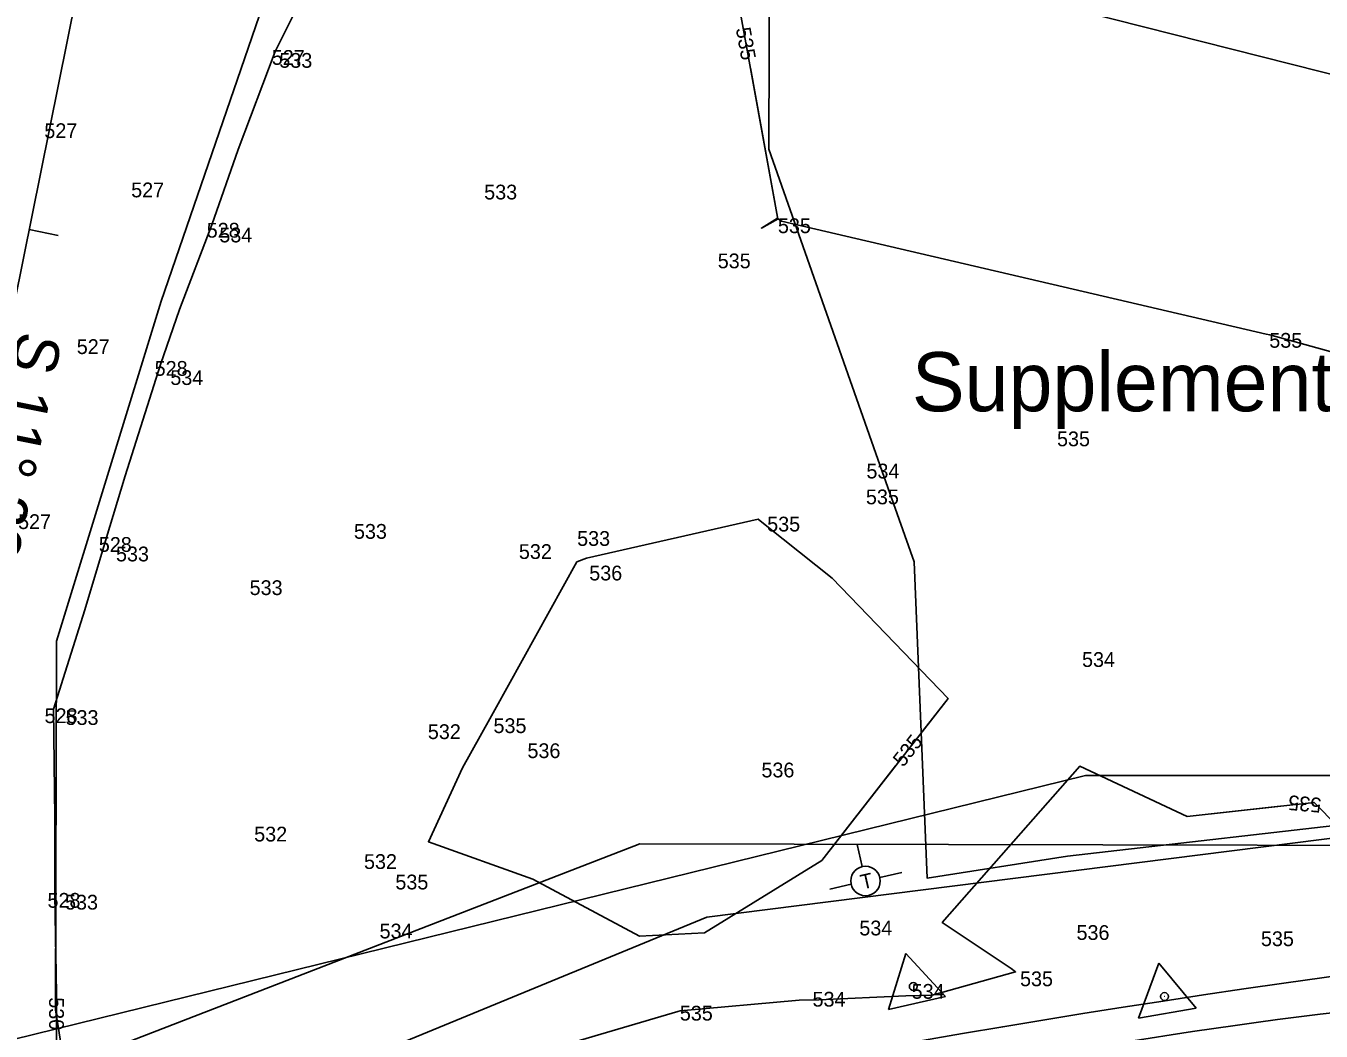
# Model space of a CAD drawing. Extents: x 1787461 to 1970323, y 938412 to 1118748.
# Drawn here: x 1967824.4 to 1967999.8, y 1117941.2 to 1118077.3 of the extents above; entities that cross this region are included whole.
import ezdxf

# ---------------------------------------------------------------- set-up
doc = ezdxf.new("R2010")
doc.units = 0
for name, color, linetype in [('Default', 7, 'Continuous'), ('HHA ADDITIONAL XSs', 7, 'Continuous'), ('Level 1', 7, 'Continuous'), ('RD_EX_DV_Prop', 7, 'Continuous'), ('RD_EX_Fence_Other', 7, 'Continuous'), ('RD_EX_H2O', 7, 'Continuous'), ('RD_EX_Road', 7, 'Continuous'), ('RD_EX_UT', 7, 'Continuous'), ('RD_EX_VEG', 7, 'Continuous'), ('RD_HC_CL', 7, 'Continuous'), ('RD_HC_Data', 7, 'Continuous'), ('RD_HC_Data_Rel', 7, 'Continuous'), ('RD_HC_Data_Tic', 7, 'Continuous'), ('RD_PD_Final_TrvlWay', 7, 'Continuous'), ('RD_SMD_Locator', 7, 'Continuous')]:
    doc.layers.add(name, color=color, linetype=linetype)

msp = doc.modelspace()

# ---------------------------------------------------------------- linework, layer by layer
at = {"layer": 'Default'}
for points in [[(1967828.54, 1117946.2), (1967828.33, 1117959.79), (1967828.34, 1117970.11), (1967828.12, 1117984.79), (1967832.39, 1117998.26), (1967835.19, 1118007.59), (1967837.84, 1118016.4), (1967842.61, 1118031.47), (1967845.22, 1118038.9), (1967849.58, 1118050.38), (1967853.13, 1118060.57), (1967858.16, 1118073.86), (1967863.11, 1118083.83), (1967868.71, 1118095.35), (1967874.84, 1118107.68), (1967879.73, 1118117.72), (1967880.44, 1118118.26), (1967881.88, 1118119.35), (1967891.88, 1118127.03), (1967894.42, 1118128.95)], [(1967828.54, 1117946.2), (1967828.33, 1117959.79), (1967828.34, 1117970.11), (1967828.12, 1117984.79), (1967832.39, 1117998.26), (1967835.19, 1118007.59), (1967837.84, 1118016.4), (1967842.61, 1118031.47), (1967845.22, 1118038.9), (1967849.58, 1118050.38), (1967853.13, 1118060.57), (1967858.16, 1118073.86), (1967863.11, 1118083.83), (1967868.71, 1118095.35), (1967874.84, 1118107.68), (1967879.73, 1118117.72), (1967880.44, 1118118.26), (1967881.88, 1118119.35), (1967891.88, 1118127.03), (1967894.42, 1118128.95)], [(1967828.54, 1117946.2), (1967828.33, 1117959.79), (1967828.34, 1117970.11), (1967828.12, 1117984.79), (1967832.39, 1117998.26), (1967835.19, 1118007.59), (1967837.84, 1118016.4), (1967842.61, 1118031.47), (1967845.22, 1118038.9), (1967849.58, 1118050.38), (1967853.13, 1118060.57), (1967858.16, 1118073.86), (1967863.11, 1118083.83), (1967868.71, 1118095.35), (1967874.84, 1118107.68), (1967879.73, 1118117.72), (1967880.44, 1118118.26), (1967881.88, 1118119.35), (1967891.88, 1118127.03), (1967894.42, 1118128.95)], [(1967828.54, 1117946.2), (1967828.33, 1117959.79), (1967828.34, 1117970.11), (1967828.12, 1117984.79), (1967832.39, 1117998.26), (1967835.19, 1118007.59), (1967837.84, 1118016.4), (1967842.61, 1118031.47), (1967845.22, 1118038.9), (1967849.58, 1118050.38), (1967853.13, 1118060.57), (1967858.16, 1118073.86), (1967863.11, 1118083.83), (1967868.71, 1118095.35), (1967874.84, 1118107.68), (1967879.73, 1118117.72), (1967880.44, 1118118.26), (1967881.88, 1118119.35), (1967891.88, 1118127.03), (1967894.42, 1118128.95)], [(1967828.54, 1117946.2), (1967828.33, 1117959.79), (1967828.34, 1117970.11), (1967828.12, 1117984.79), (1967832.39, 1117998.26), (1967835.19, 1118007.59), (1967837.84, 1118016.4), (1967842.61, 1118031.47), (1967845.22, 1118038.9), (1967849.58, 1118050.38), (1967853.13, 1118060.57), (1967858.16, 1118073.86), (1967863.11, 1118083.83), (1967868.71, 1118095.35), (1967874.84, 1118107.68), (1967879.73, 1118117.72), (1967880.44, 1118118.26), (1967881.88, 1118119.35), (1967891.88, 1118127.03), (1967894.42, 1118128.95)], [(1967828.54, 1117946.2), (1967828.33, 1117959.79), (1967828.34, 1117970.11), (1967828.12, 1117984.79), (1967832.39, 1117998.26), (1967835.19, 1118007.59), (1967837.84, 1118016.4), (1967842.61, 1118031.47), (1967845.22, 1118038.9), (1967849.58, 1118050.38), (1967853.13, 1118060.57), (1967858.16, 1118073.86), (1967863.11, 1118083.83), (1967868.71, 1118095.35), (1967874.84, 1118107.68), (1967879.73, 1118117.72), (1967880.44, 1118118.26), (1967881.88, 1118119.35), (1967891.88, 1118127.03), (1967894.42, 1118128.95)], [(1967915.91, 1118108.1), (1967926.19, 1118051.4), (1967926.18, 1118051.26), (1967924.01, 1118049.94), (1967926.27, 1118051.18), (1967926.72, 1118050.88), (1967992.39, 1118035.55), (1967992.88, 1118035.49), (1968026.69, 1118026.12), (1968042.97, 1118005.82), (1968041.62, 1117976.71), (1968051.06, 1117991.91), (1968062.41, 1117984.73), (1968055.12, 1118002.49), (1968107.9, 1117976.3), (1968127.27, 1117968.76), (1968135.27, 1117966.88), (1968158.58, 1117958.62), (1968183.42, 1117953.49), (1968183.93, 1117953.55), (1968186.05, 1117953.11), (1968208.47, 1117951.67)], [(1967828.54, 1117935.04), (1967828.55, 1117945.4), (1967828.33, 1117959.79), (1967828.34, 1117970.11), (1967828.12, 1117984.79), (1967832.39, 1117998.26), (1967835.19, 1118007.59), (1967837.84, 1118016.4), (1967842.61, 1118031.47), (1967845.22, 1118038.9), (1967849.58, 1118050.38), (1967853.13, 1118060.57), (1967858.16, 1118073.86), (1967863.11, 1118083.83)], [(1967922.52, 1118071.64), (1967926.19, 1118051.4), (1967926.18, 1118051.26), (1967924.01, 1118049.94), (1967926.27, 1118051.18), (1967926.72, 1118050.88), (1967992.39, 1118035.55), (1967992.88, 1118035.49), (1968026.69, 1118026.12), (1968042.97, 1118005.82), (1968041.62, 1117976.71), (1968049.78, 1117989.85)], [(1967922.52, 1118071.64), (1967926.19, 1118051.4), (1967926.18, 1118051.26), (1967924.01, 1118049.94), (1967926.27, 1118051.18), (1967926.72, 1118050.88), (1967992.39, 1118035.55), (1967992.88, 1118035.49), (1968026.69, 1118026.12), (1968042.97, 1118005.82), (1968041.62, 1117976.71), (1968049.78, 1117989.85)], [(1967922.52, 1118071.64), (1967926.19, 1118051.4), (1967926.18, 1118051.26), (1967924.01, 1118049.94), (1967926.27, 1118051.18), (1967926.72, 1118050.88), (1967992.39, 1118035.55), (1967992.88, 1118035.49), (1968026.69, 1118026.12), (1968042.97, 1118005.82), (1968041.62, 1117976.71), (1968049.78, 1117989.85)], [(1967922.52, 1118071.64), (1967926.19, 1118051.4), (1967926.18, 1118051.26), (1967924.01, 1118049.94), (1967926.27, 1118051.18), (1967926.72, 1118050.88), (1967992.39, 1118035.55), (1967992.88, 1118035.49), (1968026.69, 1118026.12), (1968042.97, 1118005.82), (1968041.62, 1117976.71), (1968049.78, 1117989.85)], [(1967922.52, 1118071.64), (1967926.19, 1118051.4), (1967926.18, 1118051.26), (1967924.01, 1118049.94), (1967926.27, 1118051.18), (1967926.72, 1118050.88), (1967992.39, 1118035.55), (1967992.88, 1118035.49), (1968026.69, 1118026.12), (1968042.97, 1118005.82), (1968041.62, 1117976.71), (1968049.78, 1117989.85)], [(1967922.52, 1118071.64), (1967926.19, 1118051.4), (1967926.18, 1118051.26), (1967924.01, 1118049.94), (1967926.27, 1118051.18), (1967926.72, 1118050.88), (1967992.39, 1118035.55), (1967992.88, 1118035.49), (1968026.69, 1118026.12), (1968042.97, 1118005.82), (1968041.62, 1117976.71), (1968049.78, 1117989.85)], [(1967887.9, 1117984.71), (1967887.24, 1117983.5), (1967883.53, 1117976.86), (1967878.92, 1117966.83), (1967893.06, 1117961.78), (1967907.49, 1117954.05), (1967916.29, 1117954.52), (1967932.22, 1117964.31), (1967949.29, 1117986.25), (1967933.58, 1118002.54), (1967924.77, 1118009.55), (1967923.57, 1118010.51), (1967900.34, 1118005.25), (1967899.03, 1118004.73), (1967887.9, 1117984.71)], [(1967945.86, 1117981.85), (1967949.29, 1117986.25), (1967933.58, 1118002.54), (1967924.77, 1118009.55), (1967923.57, 1118010.51), (1967900.34, 1118005.25), (1967899.03, 1118004.73), (1967887.9, 1117984.71)], [(1967945.86, 1117981.85), (1967949.29, 1117986.25), (1967933.58, 1118002.54), (1967924.77, 1118009.55), (1967923.57, 1118010.51), (1967900.34, 1118005.25), (1967899.03, 1118004.73), (1967887.9, 1117984.71)], [(1967945.86, 1117981.85), (1967949.29, 1117986.25), (1967933.58, 1118002.54), (1967924.77, 1118009.55), (1967923.57, 1118010.51), (1967900.34, 1118005.25), (1967899.03, 1118004.73), (1967887.9, 1117984.71)], [(1967945.86, 1117981.85), (1967949.29, 1117986.25), (1967933.58, 1118002.54), (1967924.77, 1118009.55), (1967923.57, 1118010.51), (1967900.34, 1118005.25), (1967899.03, 1118004.73), (1967887.9, 1117984.71)], [(1967945.86, 1117981.85), (1967949.29, 1117986.25), (1967933.58, 1118002.54), (1967924.77, 1118009.55), (1967923.57, 1118010.51), (1967900.34, 1118005.25), (1967899.03, 1118004.73), (1967887.9, 1117984.71)], [(1967945.86, 1117981.85), (1967949.29, 1117986.25), (1967933.58, 1118002.54), (1967924.77, 1118009.55), (1967923.57, 1118010.51), (1967900.34, 1118005.25), (1967899.03, 1118004.73), (1967887.9, 1117984.71)], [(1967887.9, 1117984.71), (1967887.24, 1117983.5), (1967883.53, 1117976.86), (1967878.92, 1117966.83), (1967893.06, 1117961.78), (1967907.49, 1117954.05), (1967916.29, 1117954.52), (1967932.22, 1117964.31), (1967942.17, 1117977.11)], [(1967887.9, 1117984.71), (1967887.24, 1117983.5), (1967883.53, 1117976.86), (1967878.92, 1117966.83), (1967893.06, 1117961.78), (1967907.49, 1117954.05), (1967916.29, 1117954.52), (1967932.22, 1117964.31), (1967942.17, 1117977.11)], [(1967887.9, 1117984.71), (1967887.24, 1117983.5), (1967883.53, 1117976.86), (1967878.92, 1117966.83), (1967893.06, 1117961.78), (1967907.49, 1117954.05), (1967916.29, 1117954.52), (1967932.22, 1117964.31), (1967942.17, 1117977.11)], [(1967887.9, 1117984.71), (1967887.24, 1117983.5), (1967883.53, 1117976.86), (1967878.92, 1117966.83), (1967893.06, 1117961.78), (1967907.49, 1117954.05), (1967916.29, 1117954.52), (1967932.22, 1117964.31), (1967942.17, 1117977.11)], [(1967887.9, 1117984.71), (1967887.24, 1117983.5), (1967883.53, 1117976.86), (1967878.92, 1117966.83), (1967893.06, 1117961.78), (1967907.49, 1117954.05), (1967916.29, 1117954.52), (1967932.22, 1117964.31), (1967942.17, 1117977.11)], [(1967887.9, 1117984.71), (1967887.24, 1117983.5), (1967883.53, 1117976.86), (1967878.92, 1117966.83), (1967893.06, 1117961.78), (1967907.49, 1117954.05), (1967916.29, 1117954.52), (1967932.22, 1117964.31), (1967942.17, 1117977.11)], [(1967994.28, 1117971.65), (1967981.7, 1117970.25), (1967967.13, 1117977.05), (1967948.5, 1117955.92), (1967957.82, 1117949.66), (1967958.43, 1117949.2), (1967947.15, 1117946.05), (1967943.56, 1117945.99), (1967931.77, 1117945.42), (1967929.14, 1117945.37), (1967913.02, 1117943.94), (1967912.71, 1117943.86), (1967897.21, 1117939.27), (1967891.98, 1117937.99), (1967874.97, 1117933.12), (1967873.6, 1117931.42), (1967869.61, 1117926.13), (1967868.34, 1117920.54), (1967868.62, 1117916.32), (1967868.72, 1117912.52), (1967867.34, 1117906.25), (1967867.4, 1117904.75), (1967870.79, 1117900.42), (1967873.69, 1117891.23)], [(1967994.28, 1117971.65), (1967981.7, 1117970.25), (1967967.13, 1117977.05), (1967948.5, 1117955.92), (1967957.82, 1117949.66), (1967958.43, 1117949.2), (1967947.15, 1117946.05), (1967943.56, 1117945.99), (1967931.77, 1117945.42), (1967929.14, 1117945.37), (1967913.02, 1117943.94), (1967912.71, 1117943.86), (1967897.21, 1117939.27), (1967891.98, 1117937.99), (1967874.97, 1117933.12), (1967873.6, 1117931.42), (1967869.61, 1117926.13), (1967868.34, 1117920.54), (1967868.62, 1117916.32), (1967868.72, 1117912.52), (1967867.34, 1117906.25), (1967867.4, 1117904.75), (1967870.79, 1117900.42), (1967873.69, 1117891.23)], [(1967994.28, 1117971.65), (1967981.7, 1117970.25), (1967967.13, 1117977.05), (1967948.5, 1117955.92), (1967957.82, 1117949.66), (1967958.43, 1117949.2), (1967947.15, 1117946.05), (1967943.56, 1117945.99), (1967931.77, 1117945.42), (1967929.14, 1117945.37), (1967913.02, 1117943.94), (1967912.71, 1117943.86), (1967897.21, 1117939.27), (1967891.98, 1117937.99), (1967874.97, 1117933.12), (1967873.6, 1117931.42), (1967869.61, 1117926.13), (1967868.34, 1117920.54), (1967868.62, 1117916.32), (1967868.72, 1117912.52), (1967867.34, 1117906.25), (1967867.4, 1117904.75), (1967870.79, 1117900.42), (1967873.69, 1117891.23)], [(1967994.28, 1117971.65), (1967981.7, 1117970.25), (1967967.13, 1117977.05), (1967948.5, 1117955.92), (1967957.82, 1117949.66), (1967958.43, 1117949.2), (1967947.15, 1117946.05), (1967943.56, 1117945.99), (1967931.77, 1117945.42), (1967929.14, 1117945.37), (1967913.02, 1117943.94), (1967912.71, 1117943.86), (1967897.21, 1117939.27), (1967891.98, 1117937.99), (1967874.97, 1117933.12), (1967873.6, 1117931.42), (1967869.61, 1117926.13), (1967868.34, 1117920.54), (1967868.62, 1117916.32), (1967868.72, 1117912.52), (1967867.34, 1117906.25), (1967867.4, 1117904.75), (1967870.79, 1117900.42), (1967873.69, 1117891.23)], [(1967994.28, 1117971.65), (1967981.7, 1117970.25), (1967967.13, 1117977.05), (1967948.5, 1117955.92), (1967957.82, 1117949.66), (1967958.43, 1117949.2), (1967947.15, 1117946.05), (1967943.56, 1117945.99), (1967931.77, 1117945.42), (1967929.14, 1117945.37), (1967913.02, 1117943.94), (1967912.71, 1117943.86), (1967897.21, 1117939.27), (1967891.98, 1117937.99), (1967874.97, 1117933.12), (1967873.6, 1117931.42), (1967869.61, 1117926.13), (1967868.34, 1117920.54), (1967868.62, 1117916.32), (1967868.72, 1117912.52), (1967867.34, 1117906.25), (1967867.4, 1117904.75), (1967870.79, 1117900.42), (1967873.69, 1117891.23)], [(1967994.28, 1117971.65), (1967981.7, 1117970.25), (1967967.13, 1117977.05), (1967948.5, 1117955.92), (1967957.82, 1117949.66), (1967958.43, 1117949.2), (1967947.15, 1117946.05), (1967943.56, 1117945.99), (1967931.77, 1117945.42), (1967929.14, 1117945.37), (1967913.02, 1117943.94), (1967912.71, 1117943.86), (1967897.21, 1117939.27), (1967891.98, 1117937.99), (1967874.97, 1117933.12), (1967873.6, 1117931.42), (1967869.61, 1117926.13), (1967868.34, 1117920.54), (1967868.62, 1117916.32), (1967868.72, 1117912.52), (1967867.34, 1117906.25), (1967867.4, 1117904.75), (1967870.79, 1117900.42), (1967873.69, 1117891.23)], [(1968011.41, 1117959.43), (1967998.86, 1117972.15), (1967981.7, 1117970.25), (1967967.13, 1117977.05), (1967948.5, 1117955.92), (1967957.82, 1117949.66), (1967958.43, 1117949.2), (1967947.15, 1117946.05), (1967943.56, 1117945.99), (1967931.77, 1117945.42), (1967929.14, 1117945.37), (1967913.02, 1117943.94), (1967912.71, 1117943.86), (1967897.21, 1117939.27)]]:
    msp.add_lwpolyline(points, dxfattribs=at)
at = {"layer": 'HHA ADDITIONAL XSs'}
msp.add_lwpolyline([(1969266.55, 1117963.61), (1967907.56, 1117966.55), (1967403.98, 1117771.66), (1967075.57, 1117641.84)], dxfattribs=at)
msp.add_arc((1968231.34, 1116297.54), 1667.02, 87.72663, 111.99584, dxfattribs=at)
at = {"layer": 'Level 1'}
msp.add_line((1968061.02, 1118055.58), (1967665.18, 1118155.96), dxfattribs=at)
msp.add_lwpolyline([(1968647.29, 1117975.82), (1967967.92, 1117975.82), (1967727.47, 1117916.63), (1966985.13, 1117603.01)], dxfattribs=at)
at = {"layer": 'RD_EX_DV_Prop'}
msp.add_line((1967832.81, 1118089.32), (1967803.58, 1117944.23), dxfattribs=at)
at = {"layer": 'RD_EX_Fence_Other'}
for points in [[(1967919.7, 1118378.02), (1967936.64, 1118351.76), (1967953.58, 1118310.67), (1967964.44, 1118259.92), (1967962.38, 1118197.45), (1967934.48, 1118153.92), (1967925.2, 1118115.74), (1967925.02, 1118060.61), (1967940.38, 1118016.99), (1967944.7, 1118004.73)], [(1967944.7, 1118004.73), (1967946.48, 1117961.88), (1967965.46, 1117964.9), (1968008.75, 1117969.86), (1968061.54, 1117969.15), (1968104.37, 1117971.22), (1968157.32, 1117967.69), (1968212.92, 1117965.31), (1968421.1, 1117957.24), (1968536.3, 1117952.23)]]:
    msp.add_lwpolyline(points, dxfattribs=at)
at = {"layer": 'RD_EX_H2O'}
msp.add_lwpolyline([(1967851.18, 1118399.4), (1967910.98, 1118393), (1967923.85, 1118346.18), (1967942.91, 1118303.76), (1967945.44, 1118252.51), (1967960.35, 1118200.64), (1967921.61, 1118157.98), (1967878.95, 1118126.47), (1967857.49, 1118083), (1967842.73, 1118040.05), (1967828.54, 1117994.01), (1967828.4, 1117944.09), (1967833.42, 1117912.71)], dxfattribs=at)
at = {"layer": 'RD_EX_Road'}
msp.add_arc((1968073.85, 1117330.01), 617.93, 91.49649, 100.12953, dxfattribs=at)
at = {"layer": 'RD_EX_UT'}
for p, q in [((1967936.98, 1117966.46), (1967937.66, 1117963.47)), ((1967940.06, 1117961.98), (1967943.05, 1117962.67)), ((1967933.3, 1117960.43), (1967936.16, 1117961.08))]:
    msp.add_line(p, q, dxfattribs=at)
msp.add_circle((1967938.11, 1117961.52), 2, dxfattribs=at)
at = {"layer": 'RD_EX_VEG'}
msp.add_lwpolyline([(1967420.8, 1117819.08), (1967452.15, 1117758.28), (1967558.57, 1117805.53), (1967843.24, 1117926.43), (1967916.63, 1117956.61), (1968008.44, 1117968.2), (1968060.25, 1117967.44), (1968104.58, 1117972.69), (1968157.63, 1117966.15), (1968211.15, 1117963.44), (1968421.93, 1117955.99), (1968535.19, 1117951.62)], dxfattribs=at)
at = {"layer": 'RD_HC_CL'}
msp.add_line((1967832.81, 1118089.32), (1967803.58, 1117944.23), dxfattribs=at)
at = {"layer": 'RD_HC_Data'}
for p, q in [((1967975.09, 1117942.94), (1967977.83, 1117950.4)), ((1967977.83, 1117950.4), (1967982.91, 1117944.3)), ((1967975.09, 1117942.94), (1967982.91, 1117944.3))]:
    msp.add_line(p, q, dxfattribs=at)
msp.add_circle((1967978.61, 1117945.88), 0.529, dxfattribs=at)
at = {"layer": 'RD_HC_Data_Rel'}
for p, q in [((1967941.21, 1117944.12), (1967943.57, 1117951.71)), ((1967943.57, 1117951.71), (1967948.95, 1117945.87)), ((1967941.21, 1117944.12), (1967948.95, 1117945.87))]:
    msp.add_line(p, q, dxfattribs=at)
msp.add_circle((1967944.58, 1117947.23), 0.529, dxfattribs=at)
at = {"layer": 'RD_HC_Data_Tic'}
msp.add_line((1967824.84, 1118049.74), (1967828.76, 1118048.95), dxfattribs=at)
at = {"layer": 'RD_PD_Final_TrvlWay'}
msp.add_arc((1968231.34, 1116297.54), 1648.02, 87.72663, 111.99584, dxfattribs=at)
at = {"layer": 'RD_SMD_Locator'}
msp.add_circle((1967978.61, 1117945.88), 0.001, dxfattribs=at)

# ---------------------------------------------------------------- texts
at = {"layer": 'Default'}
for s, rotation, p in [('535', 280.2756, (1967920.54, 1118076.94)), ('535', 280.2756, (1967920.54, 1118076.94)), ('535', 280.2756, (1967920.54, 1118076.94)), ('535', 280.2756, (1967920.54, 1118076.94)), ('535', 280.2756, (1967920.54, 1118076.94)), ('535', 280.2756, (1967920.54, 1118076.94)), ('535', 52.1267, (1967943.23, 1117976.83)), ('535', 52.1267, (1967943.23, 1117976.83)), ('535', 52.1267, (1967943.23, 1117976.83)), ('535', 52.1267, (1967943.23, 1117976.83)), ('535', 52.1267, (1967943.23, 1117976.83)), ('535', 52.1267, (1967943.23, 1117976.83)), ('535', 174.9722, (1967999.92, 1117972.75)), ('535', 174.9722, (1967999.92, 1117972.75)), ('535', 174.9722, (1967999.92, 1117972.75)), ('535', 174.9722, (1967999.92, 1117972.75)), ('535', 174.9722, (1967999.92, 1117972.75)), ('535', 174.9722, (1967999.92, 1117972.75)), ('530', 270.0839, (1967827.54, 1117945.77)), ('530', 270.0839, (1967827.54, 1117945.77)), ('530', 270.0839, (1967827.54, 1117945.77)), ('530', 270.0839, (1967827.54, 1117945.77)), ('530', 270.0839, (1967827.54, 1117945.77)), ('530', 270.0839, (1967827.54, 1117945.77))]:
    msp.add_text(s, height=2, rotation=rotation, dxfattribs=at).set_placement(p)
for s, p in [('527', (1967857.7, 1118072.04)), ('533', (1967858.72, 1118071.64)), ('527', (1967826.9, 1118062.12)), ('527', (1967838.66, 1118054.1)), ('533', (1967886.47, 1118053.81)), ('528', (1967848.89, 1118048.64)), ('535', (1967926.25, 1118049.25)), ('534', (1967850.6, 1118048)), ('535', (1967918.1, 1118044.49)), ('527', (1967831.29, 1118032.88)), ('535', (1967992.8, 1118033.73)), ('528', (1967841.84, 1118029.93)), ('534', (1967843.96, 1118028.69)), ('535', (1967964.05, 1118020.39)), ('534', (1967938.24, 1118016.03)), ('535', (1967938.17, 1118012.53)), ('527', (1967823.34, 1118009.18)), ('535', (1967924.8, 1118008.85)), ('533', (1967868.83, 1118007.86)), ('533', (1967899.06, 1118006.9)), ('528', (1967834.28, 1118006.09)), ('533', (1967836.6, 1118004.8)), ('532', (1967891.17, 1118005.13)), ('536', (1967900.7, 1118002.22)), ('533', (1967854.7, 1118000.24)), ('534', (1967967.44, 1117990.51)), ('528', (1967826.93, 1117982.9)), ('533', (1967829.77, 1117982.65)), ('532', (1967878.84, 1117980.74)), ('535', (1967887.73, 1117981.55)), ('536', (1967892.33, 1117978.16)), ('536', (1967924.02, 1117975.55)), ('532', (1967855.32, 1117966.87)), ('532', (1967870.19, 1117963.15)), ('535', (1967874.44, 1117960.38)), ('528', (1967827.33, 1117957.9)), ('533', (1967829.7, 1117957.65)), ('534', (1967872.3, 1117953.74)), ('534', (1967937.28, 1117954.15)), ('536', (1967966.69, 1117953.54)), ('535', (1967991.67, 1117952.7)), ('535', (1967959.04, 1117947.27)), ('534', (1967944.36, 1117945.57)), ('534', (1967930.94, 1117944.51)), ('535', (1967912.97, 1117942.62))]:
    msp.add_text(s, height=2, dxfattribs=at).set_placement(p)
at = {"layer": 'HHA ADDITIONAL XSs'}
msp.add_text('Supplemental XSC 03 Creek Station Approximately 25+20', height=8, dxfattribs=at).set_placement((1967944.4, 1118025.13))
at = {"layer": 'RD_EX_UT'}
msp.add_text('T', height=2, rotation=12.9436, dxfattribs=at).set_placement((1967937.69, 1117960.35))
at = {"layer": 'RD_HC_Data'}
msp.add_text('S 11%%d 23\' 22" W', height=6, rotation=258.6104, dxfattribs=at).set_placement((1967823.44, 1118036.17))

doc.saveas('drawing.dxf')
